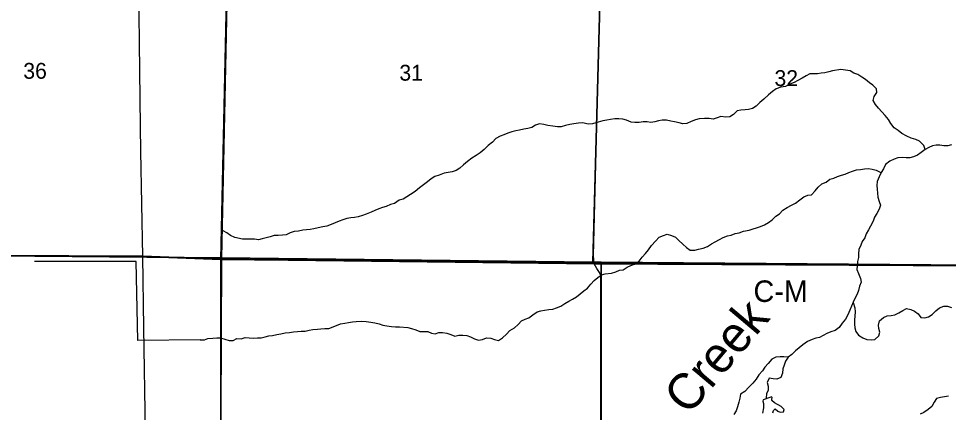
# Model space of a CAD drawing. Extents: x -6.2 to 37.4, y 0.2 to 22.2.
# Drawn here: x 2.605 to 3.834, y 15.172 to 15.692 of the extents above; entities that cross this region are included whole.
import ezdxf

# ---------------------------------------------------------------- set-up
doc = ezdxf.new("R2010")
doc.units = 0
for name, color, linetype in [('GM_X_County_Road', 7, 'Continuous'), ('GM_X_County_Road_Text', 7, 'Continuous'), ('GM_X_Minor_Lake', 7, 'Continuous'), ('GM_X_Minor_River', 7, 'Continuous'), ('GM_X_Minor_River_Text', 7, 'Continuous'), ('GM_X_Rail_Line', 7, 'Continuous'), ('GM_X_Section', 7, 'Continuous'), ('GM_X_Section_Text', 7, 'Continuous'), ('GM_X_State_Route', 7, 'Continuous'), ('GM_X_Township', 7, 'Continuous')]:
    doc.layers.add(name, color=color, linetype=linetype)

msp = doc.modelspace()

# ---------------------------------------------------------------- linework, layer by layer
at = {"layer": 'GM_X_County_Road'}
msp.add_line((2.3782, 15.3796), (2.7689, 15.3779), dxfattribs=at)
for points in [[(3.3655, 15.368), (3.3645, 15.3789), (3.372, 15.6724), (3.3775, 15.8728), (3.3853, 16.1886), (3.3901, 16.3726), (3.3905, 16.3855), (3.3907, 16.3961)], [(2.7689, 15.3779), (2.8721, 15.3739), (2.9611, 15.3728)], [(2.9611, 15.3728), (3.3655, 15.368), (3.8714, 15.3654)], [(3.3737, 14.8502), (3.3744, 15.1392), (3.374, 15.3526), (3.3724, 15.3568), (3.3688, 15.3619), (3.3655, 15.368)]]:
    msp.add_lwpolyline(points, dxfattribs=at)
at = {"layer": 'GM_X_Minor_Lake'}
msp.add_line((3.5975, 15.1916), (3.5889, 15.1886), dxfattribs=at)
for points in [[(3.6015, 15.171), (3.6023, 15.1744), (3.6047, 15.1764), (3.608, 15.1734), (3.6112, 15.1722), (3.6155, 15.1727), (3.6166, 15.1755), (3.6127, 15.1796), (3.6038, 15.1844), (3.6004, 15.1873), (3.6003, 15.1894), (3.6006, 15.1913), (3.5998, 15.1925), (3.5975, 15.1916)], [(3.5889, 15.1886), (3.5885, 15.1867), (3.5891, 15.1837), (3.5892, 15.1776), (3.5878, 15.1706)]]:
    msp.add_lwpolyline(points, dxfattribs=at)
at = {"layer": 'GM_X_Minor_River'}
for points in [[(2.8732, 15.4136), (2.8924, 16.3801)], [(3.8031, 15.519), (3.8011, 15.5245), (3.7954, 15.5302), (3.7906, 15.5324), (3.7846, 15.5341), (3.7786, 15.5368), (3.7722, 15.5404), (3.7672, 15.5441), (3.7617, 15.5479), (3.7575, 15.5533), (3.7546, 15.5589), (3.75, 15.5638), (3.7412, 15.5735), (3.7372, 15.5784), (3.7343, 15.584), (3.7356, 15.5892), (3.7388, 15.5945), (3.7387, 15.5994), (3.7339, 15.6039), (3.7291, 15.6073), (3.7239, 15.6114), (3.7191, 15.6144), (3.7139, 15.618), (3.7088, 15.62), (3.7036, 15.6228), (3.6976, 15.6239), (3.6915, 15.6247), (3.6805, 15.6231), (3.6757, 15.6217), (3.6704, 15.6204), (3.6656, 15.6197), (3.6605, 15.6191), (3.6557, 15.6189), (3.6506, 15.6192), (3.6454, 15.6165), (3.6404, 15.6135), (3.6344, 15.6104), (3.6296, 15.6077), (3.6238, 15.6054), (3.6181, 15.6025), (3.6123, 15.6012), (3.606, 15.5991), (3.6012, 15.5958), (3.5957, 15.5912), (3.5895, 15.5857), (3.5842, 15.5811), (3.5793, 15.5765), (3.5745, 15.5734), (3.5695, 15.5717), (3.5648, 15.5713), (3.5591, 15.571), (3.5543, 15.57), (3.5496, 15.5652), (3.5446, 15.562), (3.5395, 15.5617), (3.533, 15.5627), (3.5279, 15.5609), (3.5225, 15.5592), (3.5176, 15.5599), (3.5113, 15.5599), (3.5041, 15.5595), (3.4992, 15.5582), (3.4936, 15.5561), (3.4878, 15.5536), (3.4827, 15.553), (3.4776, 15.5542), (3.4716, 15.5554), (3.4665, 15.5567), (3.4612, 15.5576), (3.4553, 15.5577), (3.4502, 15.5569), (3.4454, 15.5556), (3.4403, 15.5548), (3.4354, 15.5555), (3.4301, 15.5554), (3.4247, 15.5546), (3.4192, 15.5546), (3.4141, 15.5551), (3.4083, 15.5578), (3.4031, 15.5593), (3.3978, 15.5594), (3.3926, 15.5594), (3.3871, 15.5586), (3.3823, 15.558), (3.3768, 15.5568), (3.3705, 15.5553), (3.363, 15.553), (3.3573, 15.5524), (3.3504, 15.5542), (3.3447, 15.5537), (3.3384, 15.5528), (3.3334, 15.5522), (3.3277, 15.5506), (3.3218, 15.5491), (3.3167, 15.5491), (3.3108, 15.5498), (3.3042, 15.5508), (3.2989, 15.5519), (3.2933, 15.553), (3.2879, 15.5512), (3.2829, 15.5483)], [(3.2829, 15.5483), (3.2779, 15.5466), (3.2724, 15.5458), (3.2667, 15.5448), (3.2617, 15.5436), (3.2565, 15.5423), (3.2514, 15.5407), (3.2458, 15.5386), (3.241, 15.5368), (3.2352, 15.5334), (3.2311, 15.5286), (3.2253, 15.5242), (3.2202, 15.5192), (3.2146, 15.5146), (3.2095, 15.5112), (3.2037, 15.5076), (3.1981, 15.5034), (3.1928, 15.4988), (3.188, 15.4944), (3.1828, 15.4915), (3.1778, 15.4897), (3.1724, 15.4887), (3.1673, 15.4879), (3.1606, 15.4853), (3.1548, 15.4834), (3.15, 15.4801), (3.145, 15.4764), (3.1397, 15.4726), (3.1347, 15.4686), (3.1287, 15.4638), (3.1228, 15.4598), (3.1178, 15.4564), (3.1128, 15.4533), (3.1078, 15.4521), (3.1014, 15.4479), (3.0961, 15.4464), (3.0903, 15.4439), (3.0854, 15.4425), (3.0806, 15.4406), (3.0754, 15.4386), (3.0704, 15.4361), (3.0638, 15.4335), (3.059, 15.4317), (3.0533, 15.4302), (3.0485, 15.4292), (3.0438, 15.4287), (3.0385, 15.4277), (3.0333, 15.426), (3.0283, 15.4242), (3.0179, 15.42), (3.0122, 15.4179), (3.0068, 15.4171), (3.0007, 15.4156), (2.9948, 15.4142), (2.9899, 15.4132), (2.9851, 15.413), (2.9802, 15.4127), (2.9744, 15.4114), (2.9689, 15.4108), (2.9637, 15.409), (2.9582, 15.4062), (2.9534, 15.4057), (2.9479, 15.4053), (2.9424, 15.4053), (2.937, 15.4037), (2.9319, 15.4026), (2.9267, 15.401), (2.9219, 15.3998), (2.9163, 15.4007), (2.9108, 15.4005), (2.9057, 15.4005), (2.9005, 15.4008), (2.8904, 15.403), (2.8848, 15.4056), (2.8799, 15.4092), (2.8749, 15.4116), (2.8732, 15.4136)], [(3.8378, 15.5254), (3.833, 15.524), (3.8277, 15.5239), (3.8224, 15.525), (3.8175, 15.5248), (3.8127, 15.5238), (3.8079, 15.5215), (3.8031, 15.519), (3.7976, 15.5151), (3.7928, 15.5117), (3.7874, 15.5092), (3.7826, 15.508), (3.7777, 15.5081), (3.7726, 15.5085), (3.7667, 15.5081), (3.7617, 15.5065), (3.756, 15.5036), (3.7505, 15.4991), (3.7479, 15.4936), (3.7449, 15.4886), (3.7419, 15.4828), (3.7396, 15.4768), (3.7391, 15.4713), (3.7395, 15.4666), (3.7399, 15.4614), (3.7405, 15.4559), (3.742, 15.4505), (3.744, 15.4454), (3.7423, 15.4403), (3.7389, 15.4345), (3.7359, 15.4297), (3.734, 15.4244), (3.7308, 15.4179), (3.728, 15.4128), (3.725, 15.4078), (3.7231, 15.4023), (3.7198, 15.3975), (3.7179, 15.3926), (3.7153, 15.387), (3.7147, 15.3813), (3.7146, 15.3764), (3.7135, 15.3709), (3.7131, 15.3656), (3.7126, 15.3607), (3.7147, 15.3551), (3.7172, 15.3488), (3.7185, 15.3436), (3.7163, 15.3386), (3.7146, 15.3328), (3.7128, 15.3279), (3.7101, 15.3223), (3.7077, 15.3172), (3.7056, 15.3123), (3.7032, 15.3067), (3.7007, 15.3007), (3.6975, 15.2951), (3.6932, 15.2895), (3.6894, 15.284), (3.6838, 15.2798), (3.6783, 15.278), (3.6731, 15.2761), (3.6681, 15.2734), (3.6633, 15.2709), (3.6585, 15.2697), (3.6535, 15.2683), (3.6475, 15.2655), (3.6413, 15.2609), (3.6365, 15.2572), (3.6316, 15.2532), (3.6267, 15.2484), (3.6219, 15.2448), (3.6162, 15.2451), (3.6113, 15.2451), (3.6056, 15.2447), (3.6004, 15.2422), (3.5953, 15.2366), (3.5908, 15.2316), (3.5878, 15.2268), (3.5829, 15.2214)], [(3.3157, 15.31), (3.3213, 15.3123), (3.3265, 15.3156), (3.3317, 15.3187), (3.3369, 15.3212), (3.3421, 15.3244), (3.347, 15.3286), (3.3519, 15.3323), (3.3567, 15.3361), (3.361, 15.3411), (3.3652, 15.3461), (3.3702, 15.35), (3.3751, 15.3533), (3.3798, 15.3548), (3.3882, 15.3557), (3.3939, 15.3573), (3.3988, 15.3596), (3.4037, 15.3602), (3.4089, 15.3638), (3.4139, 15.3658), (3.4187, 15.3675), (3.4249, 15.3717), (3.4287, 15.3767), (3.4332, 15.3815), (3.4373, 15.3866), (3.4411, 15.3923), (3.4464, 15.3981), (3.4513, 15.4034), (3.457, 15.4055), (3.462, 15.4071), (3.4676, 15.4056), (3.4727, 15.4032), (3.4775, 15.399), (3.4825, 15.394), (3.4875, 15.3896), (3.4923, 15.3863), (3.4985, 15.3863), (3.5035, 15.3873), (3.5096, 15.3886), (3.5152, 15.3909), (3.5204, 15.3944), (3.5254, 15.3973), (3.5312, 15.4001), (3.536, 15.4027), (3.5418, 15.405), (3.5465, 15.406), (3.5517, 15.4079), (3.5571, 15.4091), (3.5626, 15.411), (3.5704, 15.4127), (3.5854, 15.4173), (3.5904, 15.4197), (3.596, 15.4225), (3.6008, 15.4262), (3.6057, 15.4308), (3.6105, 15.4339), (3.6148, 15.4391), (3.6204, 15.4423), (3.6264, 15.4456), (3.6314, 15.4483), (3.6372, 15.4526), (3.6427, 15.4565), (3.6477, 15.4588), (3.6526, 15.4594), (3.6575, 15.4646), (3.6615, 15.4694), (3.6663, 15.4738), (3.6719, 15.4761), (3.6769, 15.48), (3.6823, 15.4813), (3.6871, 15.4836), (3.6923, 15.485), (3.697, 15.4866), (3.7022, 15.4885), (3.707, 15.4903), (3.712, 15.4922), (3.7175, 15.4926), (3.7227, 15.4936), (3.728, 15.494), (3.7329, 15.4933), (3.7382, 15.4918), (3.7434, 15.4892), (3.7449, 15.4886)], [(2.8448, 15.2675), (2.7623, 15.2669), (2.7599, 15.3709), (2.6257, 15.3712)], [(3.7076, 15.3169), (3.7099, 15.3097), (3.7105, 15.3048), (3.71, 15.2989), (3.7095, 15.294), (3.7097, 15.2885), (3.7099, 15.2836), (3.7113, 15.2786), (3.7147, 15.2737), (3.7203, 15.2702), (3.7259, 15.2681), (3.7314, 15.2676), (3.7362, 15.2682), (3.7416, 15.2728), (3.7429, 15.2777), (3.7417, 15.2824), (3.7411, 15.2872), (3.7426, 15.2927), (3.7477, 15.2973), (3.7527, 15.2992), (3.7578, 15.2998), (3.7628, 15.3008), (3.7679, 15.3031), (3.7732, 15.3066), (3.778, 15.3089), (3.7838, 15.3076), (3.7887, 15.3057), (3.7935, 15.3022), (3.7971, 15.2971), (3.8026, 15.2966), (3.8074, 15.2982), (3.8122, 15.3009), (3.8169, 15.3059), (3.822, 15.3099), (3.8274, 15.3122), (3.8325, 15.3122), (3.8376, 15.3102)], [(2.8448, 15.2675), (2.8505, 15.2677), (2.8549, 15.2693), (2.8612, 15.2699), (2.8665, 15.2703), (2.8716, 15.2702), (2.8829, 15.2668), (2.8884, 15.2668), (2.8932, 15.2695), (2.8987, 15.269), (2.904, 15.2706), (2.9093, 15.2702), (2.9156, 15.27), (2.9205, 15.2703), (2.9253, 15.2705), (2.9304, 15.2717), (2.9354, 15.2729), (2.9401, 15.2735), (2.9461, 15.2745), (2.9512, 15.2756), (2.9571, 15.277), (2.9626, 15.2772), (2.9678, 15.2784), (2.9731, 15.2786), (2.978, 15.279), (2.9832, 15.2791), (2.9887, 15.2804), (2.9935, 15.2812), (2.9996, 15.2818), (3.0043, 15.2821), (3.0092, 15.2825), (3.0146, 15.2827), (3.0249, 15.2866), (3.0301, 15.2887), (3.0356, 15.2897), (3.0406, 15.2907), (3.0459, 15.2913), (3.0509, 15.2917), (3.0573, 15.2921), (3.0638, 15.2919), (3.0702, 15.2912), (3.0756, 15.29), (3.0811, 15.2888), (3.0862, 15.2871), (3.0913, 15.2862), (3.0973, 15.2854), (3.1028, 15.2847), (3.1079, 15.2849), (3.1189, 15.2839), (3.1241, 15.2824), (3.1298, 15.2807), (3.1348, 15.2787), (3.1401, 15.2785), (3.1455, 15.2785), (3.1503, 15.2765), (3.1554, 15.2756), (3.1602, 15.2772), (3.1651, 15.2774), (3.1706, 15.2765), (3.1761, 15.2746), (3.1813, 15.2726), (3.1863, 15.2736), (3.192, 15.2736), (3.1969, 15.2732), (3.2019, 15.2714), (3.2074, 15.269), (3.2124, 15.2673), (3.2178, 15.2683), (3.2231, 15.2702), (3.2286, 15.2697), (3.2337, 15.2682), (3.2388, 15.2669), (3.244, 15.2702), (3.2493, 15.2751), (3.254, 15.2799), (3.2599, 15.2834), (3.2648, 15.288), (3.2693, 15.2928), (3.2743, 15.2949), (3.2791, 15.2968), (3.2844, 15.3007), (3.2902, 15.3047), (3.2949, 15.3059), (3.2999, 15.3069), (3.3056, 15.3078), (3.3109, 15.3083), (3.3157, 15.31)], [(3.6219, 15.2448), (3.6185, 15.2395), (3.6166, 15.2341), (3.6148, 15.2292), (3.6142, 15.2235), (3.612, 15.2181), (3.6068, 15.2156), (3.6019, 15.2163), (3.5968, 15.2168), (3.5942, 15.2114), (3.5955, 15.2066), (3.5952, 15.2011), (3.5931, 15.1963), (3.5928, 15.1912), (3.5927, 15.1899)], [(3.5829, 15.2214), (3.5793, 15.2155), (3.575, 15.2106), (3.5699, 15.2051), (3.5644, 15.1996), (3.559, 15.1959), (3.5579, 15.1907), (3.5564, 15.1852), (3.5549, 15.1792), (3.553, 15.1739), (3.5498, 15.1691)], [(3.8336, 15.1931), (3.8285, 15.1923), (3.823, 15.1915), (3.818, 15.1901), (3.815, 15.1851), (3.8116, 15.1797), (3.8068, 15.1754), (3.8011, 15.1718), (3.7961, 15.1695)]]:
    msp.add_lwpolyline(points, dxfattribs=at)
at = {"layer": 'GM_X_Rail_Line'}
for points in [[(1.6809, 18.3914), (1.6809, 15.3872), (2.0641, 15.3849), (2.2058, 15.3832), (2.3743, 15.38), (2.3781, 15.3799), (2.7688, 15.3782), (2.872, 15.3742), (2.8829, 15.8796)], [(5.0809, 15.3507), (4.8814, 15.3529), (4.368, 15.3592), (3.8713, 15.3657), (3.3654, 15.3683), (2.872, 15.3742), (2.8725, 14.8583), (2.8721, 14.3543), (2.8719, 14.3074), (5.0809, 14.3074)]]:
    msp.add_lwpolyline(points, dxfattribs=at)
msp.add_lwpolyline([(1.6809, 15.3872), (1.6809, 14.3074), (2.8719, 14.3074), (2.8721, 14.3543), (2.8725, 14.8583), (2.872, 15.3742), (2.7688, 15.3782), (2.3781, 15.3799), (2.3743, 15.38), (2.2058, 15.3832), (2.0641, 15.3849)], close=True, dxfattribs=at)
at = {"layer": 'GM_X_Section'}
for points in [[(2.8834, 15.88), (2.8728, 15.3758), (2.379, 15.3804), (2.3756, 15.3805), (2.3778, 15.8797)], [(2.8837, 15.8834), (3.3774, 15.8739), (3.3638, 15.3703), (2.8728, 15.3758), (2.8834, 15.88)], [(3.3774, 15.8739), (3.8735, 15.8683), (3.8652, 15.3662), (3.3746, 15.3703), (3.3638, 15.3703)], [(2.379, 15.3804), (2.8728, 15.3758), (2.8707, 14.8601), (2.3709, 14.8559)], [(3.3638, 15.3703), (3.3746, 15.3703), (3.3743, 14.8525), (2.8707, 14.8601), (2.8728, 15.3758)], [(3.8652, 15.3662), (3.8718, 15.3661), (3.8704, 14.8473), (3.3743, 14.8525), (3.3746, 15.3703)]]:
    msp.add_lwpolyline(points, close=True, dxfattribs=at)
at = {"layer": 'GM_X_State_Route'}
for points in [[(2.7689, 15.3779), (2.7662, 15.5169), (2.7659, 15.5491), (2.7626, 15.8093), (2.7617, 15.8809), (2.7595, 16.1086), (2.7589, 16.1911), (2.758, 16.297), (2.7568, 16.3833), (2.7569, 16.4598), (2.7561, 16.5258), (2.7557, 16.6102), (2.7556, 16.6341)], [(2.7764, 14.8602), (2.7728, 15.0826), (2.7724, 15.1131), (2.7724, 15.1461), (2.7701, 15.2835), (2.7689, 15.3779)]]:
    msp.add_lwpolyline(points, dxfattribs=at)
at = {"layer": 'GM_X_Township'}
msp.add_lwpolyline([(5.0809, 15.3507), (4.8814, 15.3529), (4.368, 15.3592), (3.8713, 15.3657), (3.3654, 15.3683), (2.872, 15.3742), (2.8829, 15.8796)], dxfattribs=at)

# ---------------------------------------------------------------- texts
at = {"layer": 'GM_X_County_Road_Text'}
msp.add_text('C-M', height=0.02841, rotation=0, dxfattribs=at).set_placement((3.576, 15.3177))
at = {"layer": 'GM_X_Minor_River_Text'}
msp.add_text('Creek', height=0.04738, rotation=49.8395, dxfattribs=at).set_placement((3.4901, 15.1665))
at = {"layer": 'GM_X_Section_Text'}
for s, p in [('36', (2.6108, 15.6125)), ('31', (3.1079, 15.61)), ('32', (3.6037, 15.6029))]:
    msp.add_text(s, height=0.02093, rotation=0, dxfattribs=at).set_placement(p)

doc.saveas('drawing.dxf')
